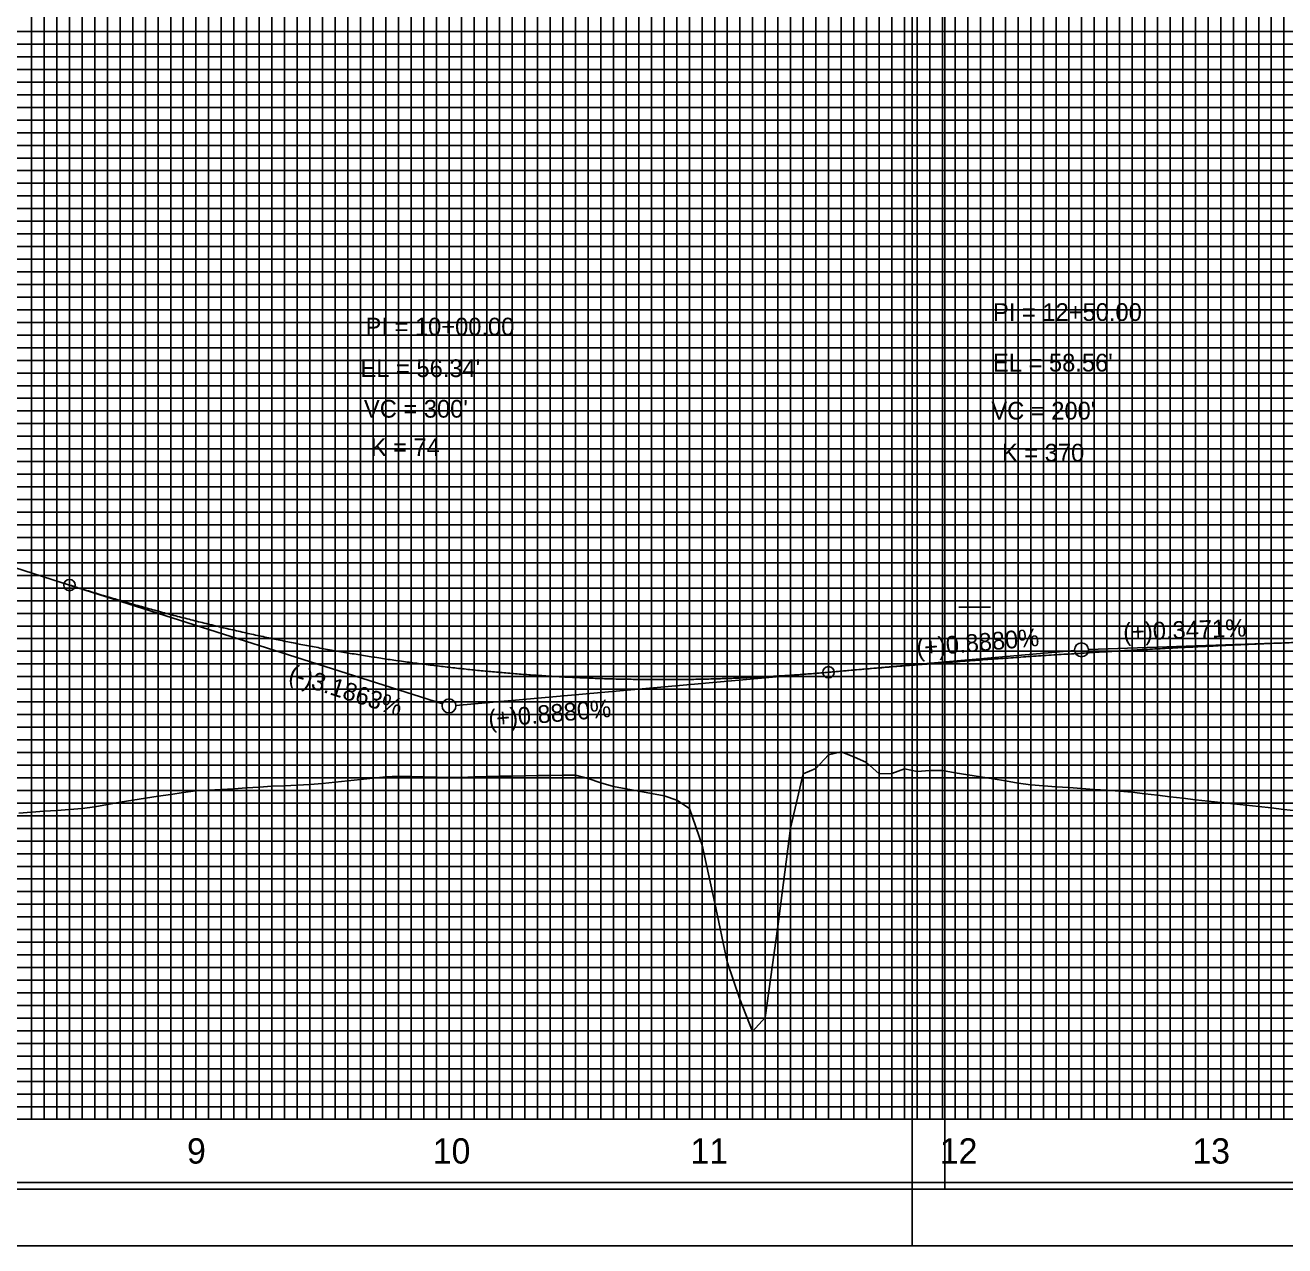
# Model space of a CAD drawing. Extents: x 2345490 to 2436403, y 465165 to 573888.
# Drawn here: x 2411727.8 to 2412225.7, y 518432.4 to 518914.9 of the extents above; entities that cross this region are included whole.
import ezdxf

# ---------------------------------------------------------------- set-up
doc = ezdxf.new("R2010")
doc.units = 0
for name, color, linetype in [('Old_Level_1', 7, 'Continuous'), ('Old_Level_18', 7, 'Continuous'), ('Old_Level_2', 7, 'Continuous'), ('Old_Level_41', 7, 'Continuous'), ('Old_Level_42', 7, 'Continuous'), ('Old_Level_43', 7, 'Continuous'), ('Old_Level_50', 7, 'Continuous'), ('Old_Level_51', 7, 'Continuous'), ('Old_Level_52', 7, 'Continuous'), ('Old_Level_63', 7, 'Continuous')]:
    doc.layers.add(name, color=color, linetype=linetype)

msp = doc.modelspace()

# ---------------------------------------------------------------- linework, layer by layer
at = {"layer": 'Old_Level_1'}
for points in [[(2411895.325, 518617.4755), (2411900.325, 518617.58925), (2411905.325, 518617.733), (2411910.325, 518617.879), (2411915.325, 518618.025), (2411920.325, 518618.09725), (2411925.325, 518618.17225), (2411930.325, 518618.24975), (2411935.325, 518618.3295), (2411940.325, 518618.412), (2411945.325, 518618.49675), (2411950.325, 518617.07825), (2411955.325, 518615.4615), (2411960.325, 518614.02275), (2411965.325, 518612.99025), (2411970.325, 518612.15675), (2411975.325, 518611.25625), (2411980.325, 518610.28925), (2411985.325, 518608.56875), (2411990.325, 518605.244), (2411995.325, 518590.789), (2412000.325, 518567.801), (2412005.325, 518544.663), (2412010.325, 518529.8745), (2412015.325, 518517.18575), (2412020.325, 518522.62375), (2412025.325, 518558.578), (2412030.325, 518597.46325), (2412035.325, 518618.9235), (2412040.325, 518621.0475), (2412045.325, 518626.507), (2412050.325, 518627.652), (2412055.325, 518625.66125), (2412060.325, 518623.461), (2412065.325, 518618.9985), (2412070.325, 518619.16825), (2412075.325, 518620.89725), (2412080.325, 518619.95825), (2412085.325, 518620.22825), (2412090.325, 518620.2535), (2412095.325, 518619.4325), (2412100.325, 518618.61075), (2412105.325, 518617.7885), (2412110.325, 518616.966), (2412115.325, 518616.14325), (2412120.325, 518615.321), (2412125.325, 518614.619), (2412130.325, 518614.249), (2412135.325, 518613.8835), (2412140.325, 518613.52275), (2412145.325, 518613.16625), (2412150.325, 518612.8145), (2412155.325, 518612.46725), (2412160.325, 518612.122), (2412165.325, 518611.67525), (2412170.325, 518611.086), (2412175.325, 518610.48375), (2412180.325, 518609.89175), (2412185.325, 518609.31025), (2412190.325, 518608.73875), (2412195.325, 518608.1775), (2412200.325, 518607.64125), (2412205.325, 518607.1465), (2412210.325, 518606.602), (2412215.325, 518606.03475), (2412220.325, 518605.47025), (2412225.325, 518604.90725), (2412230.325, 518604.3525)], [(2411725.325, 518603.45425), (2411730.325, 518603.80575), (2411735.325, 518604.1655), (2411740.325, 518604.53275), (2411745.325, 518604.90775), (2411750.325, 518605.29025), (2411755.325, 518605.964), (2411760.325, 518606.83575), (2411765.325, 518607.7175), (2411770.325, 518608.59025), (2411775.325, 518609.33825), (2411780.325, 518610.09725), (2411785.325, 518610.86675), (2411790.325, 518611.64675), (2411795.325, 518612.212), (2411800.325, 518612.5015), (2411805.325, 518612.7985), (2411810.325, 518613.10325), (2411815.325, 518613.4155), (2411820.325, 518613.735), (2411825.325, 518614.0475), (2411830.325, 518614.26175), (2411835.325, 518614.4945), (2411840.325, 518614.7595), (2411845.325, 518615.187), (2411850.325, 518615.7125), (2411855.325, 518616.235), (2411860.325, 518616.75425), (2411865.325, 518617.2705), (2411870.325, 518617.783), (2411875.325, 518618.05575), (2411880.325, 518617.9135), (2411885.325, 518617.7695), (2411890.325, 518617.62325), (2411895.325, 518617.4755)]]:
    msp.add_lwpolyline(points, dxfattribs=at)
at = {"layer": 'Old_Level_18'}
msp.add_lwpolyline([(2412345.325, 519507.40475), (2410845.325, 519507.40475), (2410845.325, 518457.40475), (2412345.325, 518457.40475)], close=True, dxfattribs=at)
at = {"layer": 'Old_Level_2'}
for p, q in [((2411225.325, 518859.28375), (2411745.325, 518693.59875)), ((2411745.325, 518693.59875), (2411892.705, 518646.64)), ((2412245.325, 518671.4755), (2412148.0735, 518668.10025)), ((2412045.325, 518659.12475), (2412142.586, 518667.76175)), ((2412045.325, 518659.12475), (2411898.06425, 518646.04825))]:
    msp.add_line(p, q, dxfattribs=at)
for centre, radius in [((2411745.325, 518693.59875), 2.25), ((2412145.325, 518668.00475), 2.75), ((2412045.325, 518659.12475), 2.25), ((2411895.325, 518645.805), 2.75)]:
    msp.add_circle(centre, radius, dxfattribs=at)
for points in [[(2411745.325, 518693.59875), (2411751.325, 518691.71125), (2411757.325, 518689.873), (2411763.325, 518688.0835), (2411769.325, 518686.34275), (2411775.325, 518684.651), (2411781.325, 518683.00825), (2411787.325, 518681.41425), (2411793.325, 518679.86925), (2411799.325, 518678.373), (2411805.325, 518676.92575), (2411811.325, 518675.52725), (2411817.325, 518674.17775), (2411823.325, 518672.87725), (2411829.325, 518671.6255), (2411835.325, 518670.4225), (2411841.325, 518669.26875), (2411847.325, 518668.1635), (2411853.325, 518667.1075), (2411859.325, 518666.10025), (2411865.325, 518665.14175), (2411871.325, 518664.23225), (2411877.325, 518663.37175), (2411883.325, 518662.56), (2411889.325, 518661.79725), (2411895.325, 518661.08325), (2411901.325, 518660.41825), (2411907.325, 518659.80225), (2411913.325, 518659.235), (2411919.325, 518658.7165), (2411925.325, 518658.247), (2411931.325, 518657.8265), (2411937.325, 518657.45475), (2411943.325, 518657.132), (2411949.325, 518656.858), (2411955.325, 518656.633), (2411961.325, 518656.457), (2411967.325, 518656.32975), (2411973.325, 518656.2515), (2411979.325, 518656.222), (2411985.325, 518656.2415), (2411991.325, 518656.30975), (2411997.325, 518656.427), (2412003.325, 518656.593), (2412009.325, 518656.808), (2412015.325, 518657.072), (2412021.325, 518657.38475), (2412027.325, 518657.7465), (2412033.325, 518658.157), (2412039.325, 518658.6165), (2412045.325, 518659.12475)], [(2412045.325, 518659.12475), (2412049.325, 518659.478), (2412053.325, 518659.8265), (2412057.325, 518660.171), (2412061.325, 518660.511), (2412065.325, 518660.84675), (2412069.325, 518661.17825), (2412073.325, 518661.50525), (2412077.325, 518661.828), (2412081.325, 518662.1465), (2412085.325, 518662.4605), (2412089.325, 518662.77025), (2412093.325, 518663.07575), (2412097.325, 518663.37675), (2412101.325, 518663.6735), (2412105.325, 518663.966), (2412109.325, 518664.25425), (2412113.325, 518664.538), (2412117.325, 518664.8175), (2412121.325, 518665.0925), (2412125.325, 518665.36325), (2412129.325, 518665.62975), (2412133.325, 518665.892), (2412137.325, 518666.14975), (2412141.325, 518666.40325), (2412145.325, 518666.6525), (2412149.325, 518666.89725), (2412153.325, 518667.138), (2412157.325, 518667.374), (2412161.325, 518667.606), (2412165.325, 518667.8335), (2412169.325, 518668.05675), (2412173.325, 518668.2755), (2412177.325, 518668.49025), (2412181.325, 518668.70025), (2412185.325, 518668.90625), (2412189.325, 518669.10775), (2412193.325, 518669.305), (2412197.325, 518669.498), (2412201.325, 518669.6865), (2412205.325, 518669.87075), (2412209.325, 518670.05075), (2412213.325, 518670.2265), (2412217.325, 518670.39775), (2412221.325, 518670.56475), (2412225.325, 518670.72725), (2412229.325, 518670.8855), (2412233.325, 518671.0395), (2412237.325, 518671.18925), (2412241.325, 518671.3345), (2412245.325, 518671.4755)]]:
    msp.add_spline(points, degree=3, dxfattribs=at)
at = {"layer": 'Old_Level_41'}
for p, q in [((2412096.825, 518684.90475), (2412109.325, 518684.90475)), ((2412345.325, 518482.40475), (2410845.325, 518482.40475))]:
    msp.add_line(p, q, dxfattribs=at)
for points in [[(2411695.325, 519507.40475), (2411695.325, 518482.40475), (2411745.325, 518482.40475), (2411745.325, 519507.40475)], [(2411770.325, 519507.40475), (2411770.325, 518482.40475), (2411820.325, 518482.40475), (2411820.325, 519507.40475)], [(2411795.325, 519507.40475), (2411795.325, 518482.40475), (2411845.325, 518482.40475), (2411845.325, 519507.40475)], [(2411870.325, 519507.40475), (2411870.325, 518482.40475), (2411920.325, 518482.40475), (2411920.325, 519507.40475)], [(2411895.325, 519507.40475), (2411895.325, 518482.40475), (2411945.325, 518482.40475), (2411945.325, 519507.40475)], [(2411970.325, 519507.40475), (2411970.325, 518482.40475), (2412020.325, 518482.40475), (2412020.325, 519507.40475)], [(2411995.325, 519507.40475), (2411995.325, 518482.40475), (2412045.325, 518482.40475), (2412045.325, 519507.40475)], [(2412070.325, 519507.40475), (2412070.325, 518482.40475), (2412120.325, 518482.40475), (2412120.325, 519507.40475)], [(2412095.325, 519507.40475), (2412095.325, 518482.40475), (2412145.325, 518482.40475), (2412145.325, 519507.40475)], [(2412170.325, 519369.85475), (2412170.325, 518482.40475), (2412220.325, 518482.40475), (2412220.325, 519369.85475)], [(2412345.325, 518907.40475), (2410845.325, 518907.40475), (2410845.325, 518857.40475), (2412345.325, 518857.40475)], [(2412345.325, 518832.40475), (2410845.325, 518832.40475), (2410845.325, 518882.40475), (2412345.325, 518882.40475)], [(2412345.325, 518807.40475), (2410845.325, 518807.40475), (2410845.325, 518757.40475), (2412345.325, 518757.40475)], [(2412345.325, 518732.40475), (2410845.325, 518732.40475), (2410845.325, 518782.40475), (2412345.325, 518782.40475)], [(2412345.325, 518707.40475), (2410845.325, 518707.40475), (2410845.325, 518657.40475), (2412345.325, 518657.40475)], [(2412345.325, 518607.40475), (2410845.325, 518607.40475), (2410845.325, 518557.40475), (2412345.325, 518557.40475)], [(2412345.325, 518532.40475), (2410845.325, 518532.40475), (2410845.325, 518582.40475), (2412345.325, 518582.40475)], [(2412345.325, 518507.40475), (2410845.325, 518507.40475)]]:
    msp.add_lwpolyline(points, dxfattribs=at)
at = {"layer": 'Old_Level_42'}
for points in [[(2412195.325, 519369.85475), (2412195.325, 518482.40475), (2412245.325, 518482.40475), (2412245.325, 519369.85475)], [(2412345.325, 518632.40475), (2410845.325, 518632.40475), (2410845.325, 518682.40475), (2412345.325, 518682.40475)]]:
    msp.add_lwpolyline(points, dxfattribs=at)
at = {"layer": 'Old_Level_43'}
for points in [[(2411730.325, 519507.40475), (2411730.325, 518482.40475), (2411735.325, 518482.40475), (2411735.325, 519507.40475)], [(2411740.325, 519507.40475), (2411740.325, 518482.40475), (2411750.325, 518482.40475), (2411750.325, 519507.40475)], [(2411755.325, 519507.40475), (2411755.325, 518482.40475), (2411760.325, 518482.40475), (2411760.325, 519507.40475)], [(2411765.325, 519507.40475), (2411765.325, 518482.40475), (2411775.325, 518482.40475), (2411775.325, 519507.40475)], [(2411780.325, 519507.40475), (2411780.325, 518482.40475), (2411785.325, 518482.40475), (2411785.325, 519507.40475)], [(2411790.325, 519507.40475), (2411790.325, 518482.40475), (2411800.325, 518482.40475), (2411800.325, 519507.40475)], [(2411805.325, 519507.40475), (2411805.325, 518482.40475), (2411810.325, 518482.40475), (2411810.325, 519507.40475)], [(2411815.325, 519507.40475), (2411815.325, 518482.40475), (2411825.325, 518482.40475), (2411825.325, 519507.40475)], [(2411830.325, 519507.40475), (2411830.325, 518482.40475), (2411835.325, 518482.40475), (2411835.325, 519507.40475)], [(2411840.325, 519507.40475), (2411840.325, 518482.40475), (2411850.325, 518482.40475), (2411850.325, 519507.40475)], [(2411855.325, 519507.40475), (2411855.325, 518482.40475), (2411860.325, 518482.40475), (2411860.325, 519507.40475)], [(2411865.325, 519507.40475), (2411865.325, 518482.40475), (2411875.325, 518482.40475), (2411875.325, 519507.40475)], [(2411880.325, 519507.40475), (2411880.325, 518482.40475), (2411885.325, 518482.40475), (2411885.325, 519507.40475)], [(2411890.325, 519507.40475), (2411890.325, 518482.40475), (2411900.325, 518482.40475), (2411900.325, 519507.40475)], [(2411905.325, 519507.40475), (2411905.325, 518482.40475), (2411910.325, 518482.40475), (2411910.325, 519507.40475)], [(2411915.325, 519507.40475), (2411915.325, 518482.40475)], [(2411915.325, 518482.40475), (2411925.325, 518482.40475), (2411925.325, 519507.40475)], [(2411930.325, 519507.40475), (2411930.325, 518482.40475), (2411935.325, 518482.40475), (2411935.325, 519507.40475)], [(2411940.325, 519507.40475), (2411940.325, 518482.40475), (2411950.325, 518482.40475), (2411950.325, 519507.40475)], [(2411955.325, 519507.40475), (2411955.325, 518482.40475), (2411960.325, 518482.40475), (2411960.325, 519507.40475)], [(2411965.325, 519507.40475), (2411965.325, 518482.40475), (2411975.325, 518482.40475), (2411975.325, 519507.40475)], [(2411980.325, 519507.40475), (2411980.325, 518482.40475), (2411985.325, 518482.40475), (2411985.325, 519507.40475)], [(2411990.325, 519507.40475), (2411990.325, 518482.40475), (2412000.325, 518482.40475), (2412000.325, 519507.40475)], [(2412005.325, 519507.40475), (2412005.325, 518482.40475), (2412010.325, 518482.40475), (2412010.325, 519507.40475)], [(2412015.325, 519507.40475), (2412015.325, 518482.40475), (2412025.325, 518482.40475), (2412025.325, 519507.40475)], [(2412030.325, 519507.40475), (2412030.325, 518482.40475), (2412035.325, 518482.40475), (2412035.325, 519507.40475)], [(2412040.325, 519507.40475), (2412040.325, 518482.40475), (2412050.325, 518482.40475), (2412050.325, 519507.40475)], [(2412055.325, 519507.40475), (2412055.325, 518482.40475), (2412060.325, 518482.40475), (2412060.325, 519507.40475)], [(2412065.325, 519507.40475), (2412065.325, 518482.40475), (2412075.325, 518482.40475), (2412075.325, 519507.40475)], [(2412080.325, 519507.40475), (2412080.325, 518482.40475), (2412085.325, 518482.40475), (2412085.325, 519507.40475)], [(2412090.325, 519507.40475), (2412090.325, 518482.40475), (2412100.325, 518482.40475), (2412100.325, 519507.40475)], [(2412105.325, 519507.40475), (2412105.325, 518482.40475), (2412110.325, 518482.40475), (2412110.325, 519507.40475)], [(2412115.325, 519507.40475), (2412115.325, 518482.40475), (2412125.325, 518482.40475), (2412125.325, 519507.40475)], [(2412130.325, 519507.40475), (2412130.325, 518482.40475), (2412135.325, 518482.40475), (2412135.325, 519507.40475)], [(2412140.325, 519507.40475), (2412140.325, 518482.40475), (2412150.325, 518482.40475), (2412150.325, 519369.85475)], [(2412155.325, 519369.85475), (2412155.325, 518482.40475), (2412160.325, 518482.40475), (2412160.325, 519369.85475)], [(2412165.325, 519369.85475), (2412165.325, 518482.40475), (2412175.325, 518482.40475), (2412175.325, 519369.85475)], [(2412180.325, 519369.85475), (2412180.325, 518482.40475), (2412185.325, 518482.40475), (2412185.325, 519369.85475)], [(2412190.325, 519369.85475), (2412190.325, 518482.40475), (2412200.325, 518482.40475), (2412200.325, 519369.85475)], [(2412205.325, 519369.85475), (2412205.325, 518482.40475), (2412210.325, 518482.40475), (2412210.325, 519369.85475)], [(2412215.325, 519369.85475), (2412215.325, 518482.40475), (2412225.325, 518482.40475), (2412225.325, 519369.85475)], [(2412295.325, 518912.40475), (2410895.325, 518912.40475), (2410895.325, 518902.40475), (2412295.325, 518902.40475)], [(2412295.325, 518897.40475), (2410895.325, 518897.40475), (2410895.325, 518892.40475), (2412295.325, 518892.40475)], [(2412295.325, 518887.40475), (2410895.325, 518887.40475), (2410895.325, 518877.40475), (2412295.325, 518877.40475)], [(2412295.325, 518872.40475), (2410895.325, 518872.40475), (2410895.325, 518867.40475), (2412295.325, 518867.40475)], [(2412295.325, 518862.40475), (2410895.325, 518862.40475), (2410895.325, 518852.40475), (2412295.325, 518852.40475)], [(2412295.325, 518847.40475), (2410895.325, 518847.40475), (2410895.325, 518842.40475), (2412295.325, 518842.40475)], [(2412295.325, 518837.40475), (2410895.325, 518837.40475), (2410895.325, 518827.40475), (2412295.325, 518827.40475)], [(2412295.325, 518822.40475), (2410895.325, 518822.40475), (2410895.325, 518817.40475), (2412295.325, 518817.40475)], [(2412295.325, 518812.40475), (2410895.325, 518812.40475), (2410895.325, 518802.40475), (2412295.325, 518802.40475)], [(2412295.325, 518797.40475), (2410895.325, 518797.40475), (2410895.325, 518792.40475), (2412295.325, 518792.40475)], [(2412295.325, 518787.40475), (2410895.325, 518787.40475), (2410895.325, 518777.40475), (2412295.325, 518777.40475)], [(2412295.325, 518772.40475), (2410895.325, 518772.40475), (2410895.325, 518767.40475), (2412295.325, 518767.40475)], [(2412295.325, 518762.40475), (2410895.325, 518762.40475), (2410895.325, 518752.40475), (2412295.325, 518752.40475)], [(2412295.325, 518747.40475), (2410895.325, 518747.40475), (2410895.325, 518742.40475), (2412295.325, 518742.40475)], [(2412295.325, 518737.40475), (2410895.325, 518737.40475), (2410895.325, 518727.40475), (2412295.325, 518727.40475)], [(2412295.325, 518722.40475), (2410895.325, 518722.40475), (2410895.325, 518717.40475), (2412295.325, 518717.40475)], [(2412295.325, 518712.40475), (2410895.325, 518712.40475), (2410895.325, 518702.40475), (2412295.325, 518702.40475)], [(2412295.325, 518697.40475), (2410895.325, 518697.40475), (2410895.325, 518692.40475), (2412295.325, 518692.40475)], [(2412295.325, 518687.40475), (2410895.325, 518687.40475)], [(2410895.325, 518677.40475), (2412295.325, 518677.40475)], [(2412295.325, 518672.40475), (2410895.325, 518672.40475), (2410895.325, 518667.40475), (2412295.325, 518667.40475)], [(2412295.325, 518662.40475), (2410895.325, 518662.40475)], [(2410895.325, 518652.40475), (2412295.325, 518652.40475)], [(2412295.325, 518647.40475), (2410895.325, 518647.40475), (2410895.325, 518642.40475), (2412295.325, 518642.40475)], [(2412295.325, 518637.40475), (2410895.325, 518637.40475), (2410895.325, 518627.40475), (2412295.325, 518627.40475)], [(2412295.325, 518622.40475), (2410895.325, 518622.40475), (2410895.325, 518617.40475), (2412295.325, 518617.40475)], [(2412295.325, 518612.40475), (2410895.325, 518612.40475), (2410895.325, 518602.40475), (2412295.325, 518602.40475)], [(2412295.325, 518597.40475), (2410895.325, 518597.40475), (2410895.325, 518592.40475), (2412295.325, 518592.40475)], [(2412295.325, 518587.40475), (2410895.325, 518587.40475), (2410895.325, 518577.40475), (2412295.325, 518577.40475)], [(2412295.325, 518572.40475), (2410895.325, 518572.40475), (2410895.325, 518567.40475), (2412295.325, 518567.40475)], [(2412295.325, 518562.40475), (2410895.325, 518562.40475), (2410895.325, 518552.40475), (2412295.325, 518552.40475)], [(2412295.325, 518547.40475), (2410895.325, 518547.40475), (2410895.325, 518542.40475), (2412295.325, 518542.40475)], [(2412295.325, 518537.40475), (2410895.325, 518537.40475), (2410895.325, 518527.40475), (2412295.325, 518527.40475)], [(2412295.325, 518522.40475), (2410895.325, 518522.40475), (2410895.325, 518517.40475), (2412295.325, 518517.40475)], [(2412295.325, 518512.40475), (2410895.325, 518512.40475), (2410895.325, 518502.40475), (2412295.325, 518502.40475)], [(2412295.325, 518497.40475), (2410895.325, 518497.40475), (2410895.325, 518492.40475), (2412295.325, 518492.40475)], [(2412295.325, 518487.40475), (2410895.325, 518487.40475)]]:
    msp.add_lwpolyline(points, dxfattribs=at)
at = {"layer": 'Old_Level_50'}
msp.add_line((2412078.325, 518432.40475), (2412078.325, 518432.40475), dxfattribs=at)
for points in [[(2412357.825, 519509.95475), (2410691.325, 519509.95475), (2410691.325, 518454.85475), (2412357.825, 518454.85475)], [(2413757.825, 519509.95475), (2412091.325, 519509.95475), (2412091.325, 518454.85475), (2413757.825, 518454.85475)]]:
    msp.add_lwpolyline(points, close=True, dxfattribs=at)
at = {"layer": 'Old_Level_51'}
for points in [[(2412362.325, 519532.40475), (2410678.325, 519532.40475), (2410678.325, 518432.40475), (2412362.325, 518432.40475)], [(2413762.325, 519532.40475), (2412078.325, 519532.40475), (2412078.325, 518432.40475), (2413762.325, 518432.40475)]]:
    msp.add_lwpolyline(points, close=True, dxfattribs=at)
at = {"layer": 'Old_Level_52'}
msp.add_line((2412091.325, 518454.85475), (2412091.325, 518454.85475), dxfattribs=at)
at = {"layer": 'Old_Level_63'}
msp.add_line((2410895.325, 518482.40475), (2412469.0995, 518482.40475), dxfattribs=at)

# ---------------------------------------------------------------- texts
at = {"layer": 'Old_Level_1'}
for s, height, p in [('9', 10, (2411791.79025, 518464.90475)), ('10', 10.000001, (2411888.9085, 518464.90475)), ('11', 10.000001, (2411990.748, 518464.90475)), ('12', 10.000001, (2412089.29625, 518464.90475)), ('13', 10.000001, (2412189.131, 518464.90475))]:
    msp.add_text(s, height=height, dxfattribs=at).set_placement(p)
at = {"layer": 'Old_Level_2'}
for s, height, p in [('PI = 12+50.00', 7.0000005, (2412110.325, 518798.00475)), ('PI = 10+00.00', 7.0000005, (2411862.34575, 518792.2685)), ("EL = 58.56'", 7.0000005, (2412110.325, 518778.00475)), ("EL = 56.34'", 7.0000005, (2411860.325, 518775.805)), ("VC = 300'", 7.000001, (2411861.69925, 518759.776)), ("VC = 200'", 7.000001, (2412109.67875, 518759.02725)), ('K = 74', 7.000001, (2411864.369, 518744.61625)), ('K = 370', 7.000001, (2412113.864, 518742.424))]:
    msp.add_text(s, height=height, dxfattribs=at).set_placement(p)
for s, rotation, p in [('(+)0.3471%', 1.9877028, (2412161.9005, 518671.582)), ('(+)0.8880%', 5.0745556, (2412080.3495, 518665.24675)), ('(-)3.1863%', 342.3268194, (2411831.44275, 518655.66425)), ('(+)0.8880%', 5.0745556, (2411911.18575, 518637.1745))]:
    msp.add_text(s, height=7.000001, rotation=rotation, dxfattribs=at).set_placement(p)

doc.saveas('drawing.dxf')
